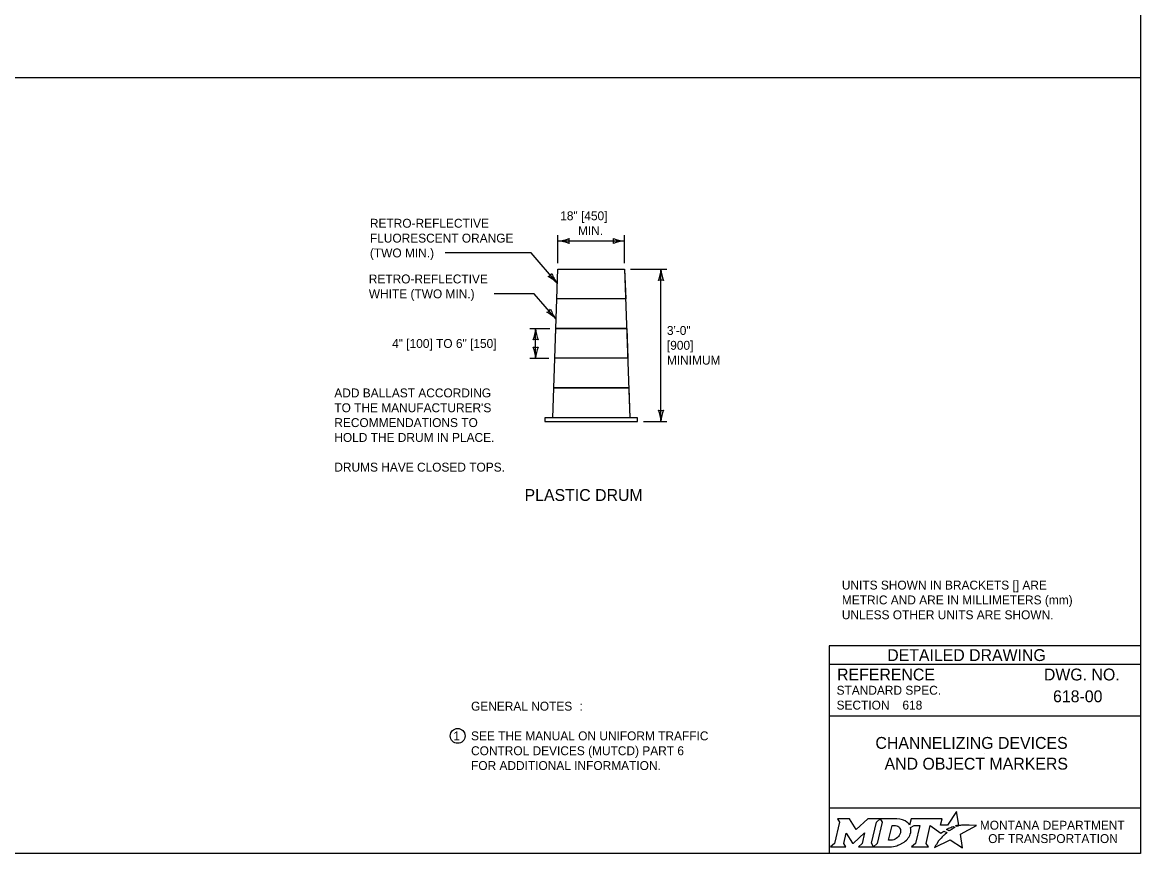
# Model space of a CAD drawing. Extents: x 49991.4 to 50024.6, y 49987.6 to 50011.4.
# Drawn here: x 50009.21 to 50016.75, y 49987.8 to 49993.4 of the extents above; entities that cross this region are included whole.
import ezdxf

# ---------------------------------------------------------------- set-up
doc = ezdxf.new("R2010")
doc.units = 0
for name, color, linetype in [('Default', 7, 'Continuous'), ('Level 1', 7, 'Continuous'), ('Level 2', 7, 'Continuous'), ('Level 3', 7, 'Continuous'), ('Level 5', 7, 'Continuous')]:
    doc.layers.add(name, color=color, linetype=linetype)

msp = doc.modelspace()

# ---------------------------------------------------------------- linework, layer by layer
at = {"layer": 'Default'}
for points in [[(50014.7056, 49988.0338), (50014.7197, 49988.0104), (50014.6862, 49987.8671), (50014.6605, 49987.8446), (50014.7621, 49987.8446), (50014.7486, 49987.8674), (50014.7648, 49987.9375), (50014.8085, 49987.8685), (50014.8138, 49987.8685), (50014.8889, 49987.938), (50014.8725, 49987.8669), (50014.8478, 49987.8449), (50014.9494, 49987.8449), (50014.9356, 49987.8682), (50014.9688, 49988.0106)], [(50014.9688, 49988.0106), (50014.9941, 49988.0338), (50014.9117, 49988.0338), (50014.8321, 49987.9608), (50014.7876, 49988.0335), (50014.7056, 49988.0338)], [(50015.1077, 49988.0338), (50014.9941, 49988.0338), (50015.0088, 49988.0109), (50014.9749, 49987.8671), (50014.9494, 49987.8449), (50015.06, 49987.8449)], [(50015.5126, 49987.9811), (50015.5023, 49987.9867), (50015.5139, 49987.9895), (50015.5255, 49987.9915), (50015.5081, 49988.0816), (50015.4486, 49987.9903), (50015.4013, 49987.9896), (50015.4116, 49988.0337), (50015.2024, 49988.0338), (50015.1923, 49987.9913), (50015.1865, 49987.9996)], [(50015.1317, 49987.9471), (50015.1305, 49987.939), (50015.1273, 49987.9297), (50015.1231, 49987.9215), (50015.1175, 49987.914), (50015.111, 49987.9071), (50015.1031, 49987.9008), (50015.0948, 49987.8961), (50015.0857, 49987.8922), (50015.0766, 49987.8899), (50015.0674, 49987.889), (50015.0515, 49987.889), (50015.0751, 49987.989), (50015.0911, 49987.989), (50015.0987, 49987.9884), (50015.1063, 49987.9865), (50015.1129, 49987.9835), (50015.119, 49987.9793), (50015.1238, 49987.9743), (50015.1275, 49987.9683), (50015.1302, 49987.9621), (50015.1318, 49987.9547), (50015.1318, 49987.9517), (50015.1317, 49987.9471)], [(50015.1991, 49987.9747), (50015.2237, 49987.9878), (50015.2606, 49987.9878), (50015.232, 49987.8673), (50015.2045, 49987.8446), (50015.3207, 49987.8446), (50015.3037, 49987.8675), (50015.3319, 49987.9877), (50015.4032, 49987.936), (50015.4243, 49987.9511), (50015.444, 49987.9402)], [(50015.3882, 49987.8843), (50015.3729, 49987.8599), (50015.3682, 49987.8524), (50015.3624, 49987.8438), (50015.3601, 49987.8395), (50015.4654, 49987.8926), (50015.5493, 49987.8375), (50015.5362, 49987.9302), (50015.6431, 49987.9886), (50015.5938, 49987.9894), (50015.5637, 49987.9898), (50015.5429, 49987.9901), (50015.5361, 49987.9886), (50015.5312, 49987.9874), (50015.5228, 49987.9851), (50015.5126, 49987.9811)], [(50015.4622, 49987.9535), (50015.4598, 49987.9518), (50015.4415, 49987.9614), (50015.4518, 49987.9671), (50015.4559, 49987.9693), (50015.4645, 49987.9733), (50015.4702, 49987.9759), (50015.4781, 49987.9789), (50015.4854, 49987.9816), (50015.4972, 49987.9742), (50015.4932, 49987.9721), (50015.4886, 49987.9696), (50015.4844, 49987.9674), (50015.4794, 49987.9645), (50015.4775, 49987.9634), (50015.4748, 49987.9618), (50015.4723, 49987.9604), (50015.47, 49987.9588), (50015.4674, 49987.957), (50015.4647, 49987.9552), (50015.4622, 49987.9535)], [(50015.1057, 49987.8522), (50015.1141, 49987.8548), (50015.1271, 49987.8602), (50015.1475, 49987.8712)], [(50015.4021, 49987.9004), (50015.4021, 49987.9004)]]:
    msp.add_lwpolyline(points, dxfattribs=at)
for centre, radius, start, end in [((50015.1308, 49987.9554), 0.0709, 339.53292, 15.85821), ((50015.0868, 49987.9727), 0.1183, 300.91025, 339.13831)]:
    msp.add_arc(centre, radius, start, end, dxfattribs=at)
for centre, major_axis, ratio, start_param, end_param in [((50015.1056, 49987.9864), (0.0834, -0.0037), 0.568097, 0.61298, 1.570796), ((50015.1612, 49987.9937), (0.0361, -0.0295), 0.469099, 1.225588, 1.570796), ((50015.3952, 49987.8923), (-0.00694, -0.00806), 0.008222, 0, 3.137361), ((50015.4119, 49987.9106), (-0.0098, -0.0102), 0.016458, 3.141593, 6.279097), ((50015.4329, 49987.9305), (-0.0112, -0.0097), 0.021651, 3.157348, 6.283185), ((50015.0603, 49987.9932), (0, 0.1484), 0.987302, 3.139398, 3.456847)]:
    msp.add_ellipse(centre, major_axis=major_axis, ratio=ratio, start_param=start_param, end_param=end_param, dxfattribs=at)
at = {"layer": 'Level 1'}
for p, q in [((50013.2787, 49991.5358), (50012.8147, 49991.5358)), ((50013.2857, 49991.3358), (50012.8077, 49991.3358)), ((50013.2927, 49991.1358), (50012.8007, 49991.1358)), ((50013.2997, 49990.9358), (50012.7937, 49990.9358))]:
    msp.add_line(p, q, dxfattribs=at)
msp.add_lwpolyline([(49999.3835, 49998.9992), (50016.7501, 49998.9992), (50016.7501, 49987.7988), (49999.3835, 49987.7988)], close=True, dxfattribs=at)
at = {"layer": 'Level 2'}
for p, q in [((49999.3835, 49993.0275), (50016.7501, 49993.0275)), ((50013.2787, 49991.5358), (50012.8147, 49991.5358)), ((50012.8007, 49991.1358), (50012.8077, 49991.3358)), ((50012.8077, 49991.3358), (50013.2857, 49991.3358)), ((50013.2857, 49991.3358), (50013.2927, 49991.1358)), ((50013.2927, 49991.1358), (50012.8007, 49991.1358)), ((50013.2997, 49990.9358), (50012.8057, 49990.9358)), ((50012.8057, 49990.9358), (50013.2997, 49990.9358))]:
    msp.add_line(p, q, dxfattribs=at)
for points in [[(50013.3067, 49990.7358), (50012.7867, 49990.7358), (50012.8217, 49991.7358), (50013.2717, 49991.7358)], [(50013.2997, 49990.9358), (50013.3067, 49990.7358), (50012.7867, 49990.7358), (50012.7937, 49990.9358), (50013.2877, 49990.9358)], [(50012.7342, 49990.7108), (50013.3592, 49990.7108), (50013.3592, 49990.7358), (50012.7342, 49990.7358)]]:
    msp.add_lwpolyline(points, close=True, dxfattribs=at)
msp.add_lwpolyline([(50012.8147, 49991.5358), (50012.8217, 49991.7358), (50013.2717, 49991.7358), (50013.2787, 49991.5358)], dxfattribs=at)
msp.add_circle((50012.1463, 49988.592), 0.05, dxfattribs=at)
at = {"layer": 'Level 3'}
for p, q in [((50012.8217, 49991.7758), (50012.8217, 49991.9658)), ((50013.2717, 49991.7758), (50013.2717, 49991.9658)), ((50013.2717, 49991.9258), (50012.8217, 49991.9258)), ((50012.6406, 49991.8455), (50012.0614, 49991.8455)), ((50012.8184, 49991.6397), (50012.6406, 49991.8455)), ((50013.3117, 49991.7358), (50013.5566, 49991.7358)), ((50013.5166, 49990.7108), (50013.5166, 49991.7358)), ((50012.6621, 49991.5703), (50012.3914, 49991.5703)), ((50012.81, 49991.3993), (50012.6621, 49991.5703)), ((50012.6317, 49991.3358), (50012.7677, 49991.3358)), ((50012.6717, 49991.1358), (50012.6717, 49991.3358)), ((50012.6317, 49991.1358), (50012.7607, 49991.1358)), ((50013.3992, 49990.7108), (50013.5566, 49990.7108))]:
    msp.add_line(p, q, dxfattribs=at)
for centre, radius, start, end in [((50012.8126, 49992.1479), 0.2223, 272.36048, 292.54399), ((50012.9499, 49991.9258), 0.0548, 162.13882, 197.86118), ((50013.1435, 49991.9258), 0.0548, 342.13882, 17.86118), ((50013.2832, 49992.1585), 0.233, 247.92284, 267.17269), ((50012.8102, 49991.6931), 0.233, 67.92284, 87.17269), ((50013.2809, 49991.7037), 0.2223, 92.36048, 112.54399), ((50013.2839, 49991.7473), 0.233, 337.92284, 357.17269), ((50013.7388, 49991.745), 0.2223, 182.36048, 202.54399), ((50012.7345, 49991.7367), 0.0548, 292.96422, 328.68658), ((50012.6563, 49991.4875), 0.2223, 43.18588, 63.36939), ((50013.002, 49991.7831), 0.233, 198.74824, 217.99809), ((50013.5166, 49991.6076), 0.0548, 72.13882, 107.86118), ((50012.7261, 49991.4963), 0.0548, 292.96924, 328.69161), ((50012.6479, 49991.2471), 0.2223, 43.19091, 63.37441), ((50012.9936, 49991.5427), 0.233, 198.75326, 218.00311), ((50012.439, 49991.3473), 0.233, 337.92284, 357.17269), ((50012.6717, 49991.2076), 0.0548, 72.13882, 107.86118), ((50012.8939, 49991.345), 0.2223, 182.36048, 202.54399), ((50012.4496, 49991.1266), 0.2223, 2.36048, 22.54399), ((50012.6717, 49991.264), 0.0548, 252.13882, 287.86118), ((50012.9044, 49991.1243), 0.233, 157.92284, 177.17269), ((50013.2945, 49990.7016), 0.2223, 2.36048, 22.54399), ((50013.5166, 49990.839), 0.0548, 252.13882, 287.86118), ((50013.7493, 49990.6993), 0.233, 157.92284, 177.17269)]:
    msp.add_arc(centre, radius, start, end, dxfattribs=at)
at = {"layer": 'Level 5'}
for p, q in [((50016.7501, 49989.1988), (50014.6501, 49989.1988)), ((50014.6501, 49989.1988), (50014.6501, 49987.7988)), ((50016.7501, 49989.0738), (50014.6501, 49989.0738)), ((50016.3862, 49988.8587), (50016.3862, 49988.8587)), ((50015.1444, 49988.7993), (50015.1444, 49988.7993)), ((50016.7501, 49988.7238), (50014.6501, 49988.7238)), ((50015.7001, 49988.4747), (50015.7001, 49988.4747)), ((50016.7501, 49988.1057), (50014.6501, 49988.1057))]:
    msp.add_line(p, q, dxfattribs=at)

# ---------------------------------------------------------------- texts
at = {"layer": 'Default'}
for s, p in [('MONTANA DEPARTMENT', (50015.6663, 49987.96)), ('OF TRANSPORTATION', (50015.7225, 49987.87))]:
    msp.add_text(s, height=0.06, dxfattribs=at).set_placement(p)
at = {"layer": 'Level 2'}
for s, height, p in [('18" [450]', 0.06, (50012.8374, 49992.0658)), ('RETRO-REFLECTIVE', 0.06, (50011.5546, 49992.0155)), ('MIN.', 0.06, (50012.957, 49991.9658)), ('FLUORESCENT ORANGE ', 0.06, (50011.5546, 49991.9155)), ('(TWO MIN.)', 0.06, (50011.5546, 49991.8155)), ('RETRO-REFLECTIVE', 0.06, (50011.5471, 49991.6403)), ('WHITE (TWO MIN.)', 0.06, (50011.5471, 49991.5403)), ('3\'-0"', 0.06, (50013.5566, 49991.2933)), ('4" [100] TO 6" [150]', 0.06, (50011.7043, 49991.2058)), ('[900]', 0.06, (50013.5566, 49991.1933)), ('MINIMUM', 0.06, (50013.5566, 49991.0933)), ('ADD BALLAST ACCORDING', 0.06, (50011.3146, 49990.8726)), ("TO THE MANUFACTURER'S", 0.06, (50011.3146, 49990.7726)), ('RECOMMENDATIONS TO', 0.06, (50011.3146, 49990.6726)), ('HOLD THE DRUM IN PLACE.', 0.06, (50011.3146, 49990.5726)), ('DRUMS HAVE CLOSED TOPS.', 0.06, (50011.3146, 49990.3726)), ('PLASTIC DRUM', 0.08, (50012.597, 49990.1747)), ('UNITS SHOWN IN BRACKETS [] ARE ', 0.06, (50014.736, 49989.5779)), ('METRIC AND ARE IN MILLIMETERS (mm) ', 0.06, (50014.736, 49989.4779)), ('UNLESS OTHER UNITS ARE SHOWN.', 0.06, (50014.736, 49989.3779)), ('618-00', 0.08, (50016.1596, 49988.8187)), ('GENERAL NOTES', 0.06, (50012.2363, 49988.762)), (':', 0.06, (50012.9671, 49988.762)), ('618', 0.06, (50015.1444, 49988.7693)), ('1', 0.06, (50012.1169, 49988.562)), ('SEE THE MANUAL ON UNIFORM TRAFFIC', 0.06, (50012.2363, 49988.562)), ('CHANNELIZING DEVICES', 0.08, (50014.9623, 49988.5047)), ('CONTROL DEVICES (MUTCD) PART 6', 0.06, (50012.2363, 49988.462)), ('FOR ADDITIONAL INFORMATION.', 0.06, (50012.2363, 49988.362)), ('AND OBJECT MARKERS', 0.08, (50015.0238, 49988.3647))]:
    msp.add_text(s, height=height, dxfattribs=at).set_placement(p)
at = {"layer": 'Level 5'}
for s, height, p in [('DETAILED DRAWING', 0.0799, (50015.0418, 49989.0963)), ('REFERENCE', 0.08, (50014.7037, 49988.9654)), ('DWG. NO.', 0.08, (50016.0979, 49988.9654)), ('STANDARD SPEC.', 0.06, (50014.7004, 49988.8694)), ('SECTION', 0.06, (50014.7004, 49988.7694))]:
    msp.add_text(s, height=height, dxfattribs=at).set_placement(p)

doc.saveas('drawing.dxf')
